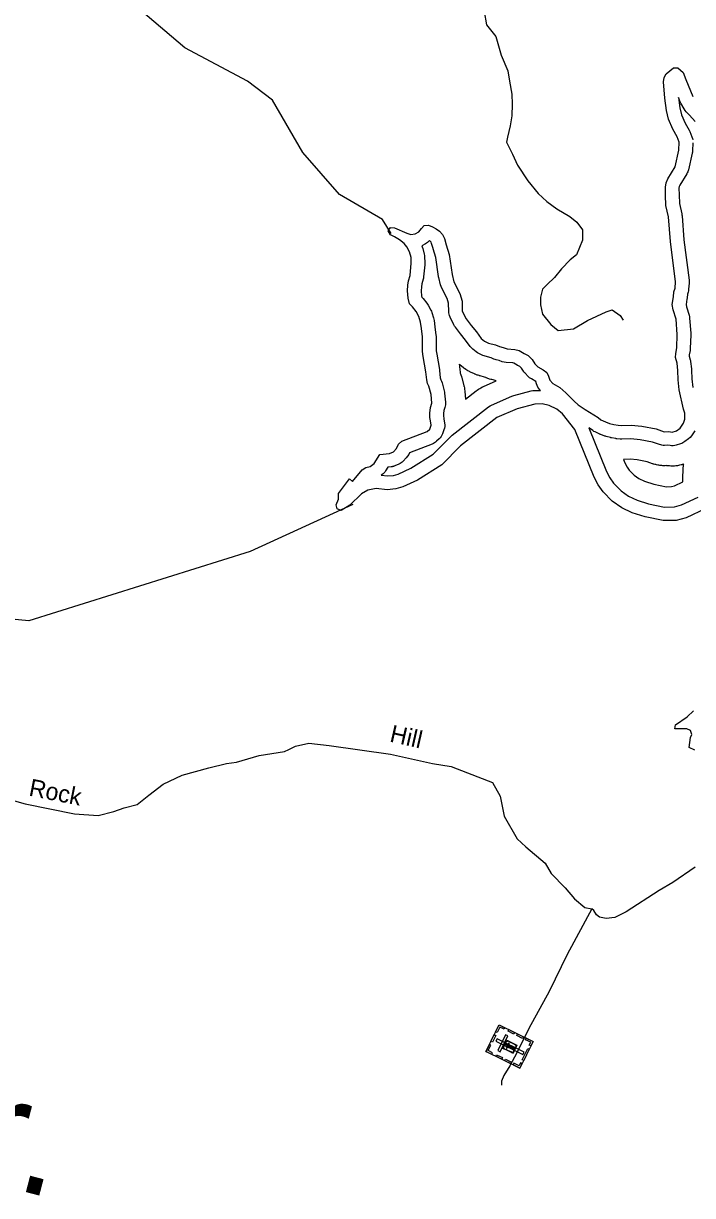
# Model space of a CAD drawing. Extents: x 1113032 to 1302912, y 664689 to 832535.
# Drawn here: x 1142627 to 1146316, y 741484 to 747949 of the extents above; entities that cross this region are included whole.
import ezdxf

# ---------------------------------------------------------------- set-up
doc = ezdxf.new("R2010")
doc.units = 0
for name, color, linetype in [('Exist Cultural Cemetery CELL', 7, 'Continuous'), ('Exist Hydrographic Buffer Line', 7, 'Continuous'), ('Exist Hydrographic Creek Single Shore', 7, 'Continuous'), ('Exist Hydrographic Creek Single Shore Label', 7, 'Continuous'), ('Exist Hydrographic Lake Shore', 7, 'Continuous'), ('Exist Road Non-System Type 51', 7, 'Continuous'), ('Exist Road Non-System Type 51 Label', 7, 'Continuous')]:
    doc.layers.add(name, color=color, linetype=linetype)

msp = doc.modelspace()

# ---------------------------------------------------------------- linework, layer by layer
at = {"layer": 'Exist Cultural Cemetery CELL'}
for points in [[(1145177, 742279), (1145249.1, 742425.5), (1145436.5, 742333.3), (1145364.4, 742186.8)], [(1145281, 742409.9), (1145276.9, 742401.5), (1145253.2, 742413.2), (1145238.5, 742383.3), (1145230.3, 742387.4), (1145249.1, 742425.5)], [(1145330.7, 742375), (1145298.8, 742390.7), (1145302.9, 742399.1), (1145334.8, 742383.4)], [(1145203.8, 742333.5), (1145222.6, 742371.6), (1145231, 742367.5), (1145212.2, 742329.4)], [(1145238, 742348.6), (1145231.3, 742334.9), (1145380.5, 742261.5), (1145387.3, 742275.2)], [(1145241.9, 742284.4), (1145255.6, 742277.6), (1145298.2, 742364.3), (1145284.5, 742371.1)], [(1145269, 742297.1), (1145290.9, 742341.8), (1145348, 742313.7), (1145326.1, 742269)], [(1145300.7, 742337), (1145299.4, 742334.5), (1145292.2, 742338), (1145287.7, 742328.9), (1145285.2, 742330.1), (1145290.9, 742341.8)], [(1145315.8, 742326.4), (1145306.1, 742331.2), (1145307.3, 742333.7), (1145317.1, 742328.9)], [(1145379.2, 742351.1), (1145347.3, 742366.8), (1145351.4, 742375.2), (1145383.3, 742359.5)], [(1145424.5, 742309), (1145416, 742313.1), (1145424, 742329.3), (1145394.3, 742343.9), (1145398.3, 742352.1), (1145436.5, 742333.3)], [(1145208.9, 742263.3), (1145213, 742271.7), (1145189.3, 742283.3), (1145204, 742313.2), (1145195.8, 742317.2), (1145177, 742279)], [(1145278.7, 742292.3), (1145279.9, 742294.9), (1145272.7, 742298.4), (1145277.2, 742307.5), (1145274.7, 742308.7), (1145269, 742297.1)], [(1145277.1, 742313.7), (1145282.9, 742325.3), (1145285.4, 742324.1), (1145279.7, 742312.5)], [(1145287.6, 742318.3), (1145285.5, 742314.1), (1145331, 742291.8), (1145333.1, 742296)], [(1145295.3, 742284.1), (1145285.6, 742288.9), (1145286.8, 742291.5), (1145296.6, 742286.7)], [(1145288.7, 742298.7), (1145292.9, 742296.7), (1145305.9, 742323.1), (1145301.7, 742325.2)], [(1145310.4, 742276.7), (1145300.7, 742281.5), (1145301.9, 742284), (1145311.6, 742279.3)], [(1145329.7, 742276.4), (1145327.1, 742277.7), (1145324.7, 742272.8), (1145315.6, 742277.2), (1145314.4, 742274.7), (1145326.1, 742269)], [(1145330.6, 742319.1), (1145320.9, 742323.9), (1145322.1, 742326.4), (1145331.8, 742321.6)], [(1145329.8, 742283.2), (1145339.2, 742302.2), (1145341.8, 742300.9), (1145332.4, 742281.9)], [(1145344.4, 742306.2), (1145341.8, 742307.5), (1145344.2, 742312.4), (1145335.2, 742316.9), (1145336.4, 742319.4), (1145348, 742313.7)], [(1145376.8, 742233.3), (1145407.5, 742295.7), (1145415.9, 742291.6), (1145385.1, 742229.1)], [(1145263.4, 742236.5), (1145231.6, 742252.1), (1145235.7, 742260.5), (1145267.6, 742244.8)], [(1145312.9, 742212.1), (1145281, 742227.8), (1145285.2, 742236.2), (1145317, 742220.5)], [(1145376.3, 742211.2), (1145367.9, 742215.3), (1145359.9, 742199.1), (1145330.2, 742213.8), (1145326.1, 742205.6), (1145364.3, 742186.8)]]:
    msp.add_lwpolyline(points, close=True, dxfattribs=at)
at = {"layer": 'Exist Hydrographic Buffer Line'}
for points in [[(1146330.2, 747407.6), (1146299.7, 747443.1), (1146281.7, 747461.3), (1146275, 747469.1), (1146269.5, 747477.8), (1146251.8, 747509.8), (1146249.8, 747513.7), (1146248.1, 747517.6), (1146238.5, 747541.2), (1146246.4, 747483), (1146255.8, 747445.3), (1146275, 747399.4), (1146296.7, 747360), (1146298.6, 747356.2), (1146300.4, 747352.4), (1146312.5, 747322.9), (1146315.2, 747315.1), (1146317, 747307)], [(1146318, 747290.4), (1146315.6, 747246.1), (1146315, 747239.8), (1146313.9, 747233.6), (1146293.3, 747142.1), (1146291.7, 747136.1), (1146289.6, 747130.3), (1146287, 747124.6), (1146283.9, 747119.2), (1146246.2, 747058), (1146242.6, 747049.3), (1146241.2, 747040.7), (1146241.7, 747003.8), (1146243.5, 746955.8), (1146256.6, 746899.9), (1146257.6, 746894.3), (1146258.3, 746888.7), (1146268.7, 746754.9), (1146297, 746533.3), (1146297.6, 746525.2), (1146297.3, 746517), (1146294.2, 746483), (1146293.1, 746475.2), (1146291.1, 746467.5), (1146287.4, 746455.3), (1146285.9, 746435.1), (1146285.6, 746431.7), (1146285.1, 746428.3), (1146280.2, 746398.3), (1146281.9, 746386.4), (1146296.6, 746339.7), (1146298.7, 746331.5), (1146299.8, 746323.2), (1146306.4, 746240.1), (1146306.6, 746235.8), (1146306.6, 746231.4), (1146303.8, 746156.4), (1146303.4, 746151.1), (1146302.6, 746145.7), (1146298.2, 746121.3), (1146297.9, 746114.4), (1146303.2, 746094.1), (1146304.3, 746089.2), (1146305, 746084.3), (1146310, 746043.8), (1146310.3, 746040.2), (1146310.5, 746036.5), (1146311.5, 745989.5), (1146317.2, 745940.8)], [(1146328, 745701.5), (1146310, 745675.2), (1146302.7, 745666.2), (1146294.1, 745658.4), (1146273.7, 745642.5), (1146268.2, 745638.7), (1146262.4, 745635.3), (1146256.3, 745632.4), (1146249.9, 745630.2), (1146226.4, 745622.9), (1146218.1, 745620.8), (1146209.5, 745619.7), (1146200.8, 745619.6), (1146192.2, 745620.5), (1146180.2, 745622.4), (1146161.5, 745621.8), (1146154.4, 745621.9), (1146147.4, 745622.7), (1146140.5, 745624.1), (1146133.7, 745626.2), (1146095.4, 745639.9), (1146026.6, 745653.3), (1145975.4, 745657.7), (1145926.4, 745656.2), (1145921.6, 745656.3), (1145916.8, 745656.6), (1145898.3, 745658.4), (1145895.5, 745658.8), (1145892.7, 745659.2), (1145869, 745663.4), (1145865.9, 745664), (1145862.9, 745664.8), (1145839.7, 745670.9), (1145836.4, 745671.9), (1145833.1, 745673), (1145810.6, 745681.2), (1145807.4, 745682.4), (1145804.3, 745683.8), (1145778.7, 745695.9), (1145772.4, 745699.3), (1145766.5, 745703.2), (1145753.4, 745712.8), (1145744.2, 745718.5), (1145840.8, 745478.2), (1145859.2, 745443.6), (1145880.7, 745413.3), (1145922.1, 745371.1), (1145963.6, 745341.9), (1146010.6, 745319.6), (1146074, 745300.2), (1146161.8, 745281.9), (1146215.9, 745282.8), (1146254.7, 745293.2), (1146347.2, 745336.2)]]:
    msp.add_lwpolyline(points, dxfattribs=at)
for points in [[(1144634, 745453), (1144666.7, 745455.6), (1144692.2, 745463.1), (1144763.5, 745495.9), (1144886.4, 745573.7), (1144983, 745671.5), (1144986.6, 745674.8), (1144990.3, 745677.9), (1145191.8, 745834.7), (1145199.6, 745840), (1145208, 745844.3), (1145320.1, 745892.8), (1145325.1, 745894.7), (1145330.3, 745896.3), (1145426.6, 745922.4), (1145436, 745924.3), (1145445.7, 745925), (1145477.7, 745925.2), (1145474.4, 745928.7), (1145468.3, 745935.8), (1145463.1, 745943.7), (1145459, 745952.1), (1145455.9, 745961), (1145452.2, 745974.9), (1145427.3, 745988.5), (1145417.8, 745994.7), (1145409.3, 746002.2), (1145392.7, 746019.4), (1145388, 746024.8), (1145383.8, 746030.7), (1145372.9, 746047.5), (1145364, 746056.3), (1145352.1, 746062.6), (1145350.8, 746063.3), (1145349.6, 746064), (1145331, 746074.7), (1145324.3, 746076.4), (1145289, 746078.7), (1145277.9, 746080.3), (1145267.2, 746083.5), (1145249.2, 746090.4), (1145233.9, 746094), (1145227.2, 746095.8), (1145220.8, 746098.3), (1145205.2, 746105.1), (1145172.5, 746113.6), (1145166.3, 746115.5), (1145160.3, 746117.9), (1145138.5, 746127.9), (1145130.2, 746132.3), (1145122.5, 746137.7), (1145103.9, 746152.7), (1145096.6, 746159.4), (1145090.3, 746167), (1145065, 746201.7), (1145036.8, 746236.6), (1145036.3, 746237.2), (1145035.8, 746237.8), (1145008.2, 746273.4), (1145003.8, 746279.9), (1145000, 746286.7), (1144979.1, 746330), (1144976, 746337.4), (1144973.7, 746345.2), (1144972.2, 746353.2), (1144971.6, 746361.2), (1144970.8, 746406.9), (1144963.6, 746432.3), (1144933.2, 746489.2), (1144929.2, 746497.9), (1144926.4, 746507), (1144916.8, 746547.2), (1144916.1, 746550.5), (1144915.5, 746553.8), (1144900.1, 746658.5), (1144885.7, 746706.1), (1144885.4, 746707.1), (1144885.1, 746708.1), (1144877.4, 746736.2), (1144873.9, 746743), (1144870.1, 746747.7), (1144864.9, 746751.4), (1144860.8, 746746.8), (1144855.3, 746741.7), (1144849.4, 746737.3), (1144843, 746733.4), (1144822.5, 746722.4), (1144825.3, 746716.3), (1144828, 746708.3), (1144836.3, 746677.5), (1144837.9, 746669.6), (1144838.8, 746661.6), (1144840.3, 746629.7), (1144840.4, 746624), (1144840, 746618.4), (1144833, 746550.7), (1144832.1, 746544.5), (1144830.7, 746538.4), (1144823.6, 746512.7), (1144820.7, 746496.5), (1144819.2, 746474.5), (1144821.5, 746445.6), (1144822.6, 746441), (1144823.4, 746440.2), (1144827.5, 746436.1), (1144831.2, 746431.7), (1144850.9, 746406.5), (1144854.7, 746401.2), (1144858, 746395.7), (1144873.1, 746367.5), (1144875.9, 746361.5), (1144878.3, 746355.3), (1144888.1, 746324.9), (1144889.9, 746318.3), (1144891.1, 746311.5), (1144895.7, 746276.2), (1144895.8, 746275.9), (1144895.8, 746275.7), (1144901.4, 746230.4), (1144901.8, 746226.6), (1144902, 746222.8), (1144902.8, 746185.5), (1144902.8, 746184.1), (1144902.8, 746182.8), (1144902.3, 746143.9), (1144905.2, 746124.1), (1144920.1, 746041), (1144920.6, 746037.9), (1144921, 746034.8), (1144924.8, 745994.3), (1144925.7, 745989), (1144928.4, 745983.9), (1144932.1, 745976), (1144934.9, 745967.6), (1144947, 745921.9), (1144948.4, 745915.5), (1144949.2, 745909.1), (1144953.3, 745860.5), (1144953.6, 745852.8), (1144953, 745845.2), (1144951.7, 745837.6), (1144949.6, 745830.2), (1144944.5, 745815), (1144942.3, 745797), (1144942.8, 745784), (1144945.2, 745770.2), (1144945.3, 745769.5), (1144945.4, 745768.8), (1144949, 745745.3), (1144949.9, 745736), (1144949.5, 745726.6), (1144948, 745717.4), (1144945.4, 745708.4), (1144937.3, 745686.1), (1144933.9, 745678.1), (1144929.5, 745670.6), (1144924.4, 745663.6), (1144918.5, 745657.3), (1144904.9, 745644.5), (1144899.4, 745639.7), (1144893.4, 745635.5), (1144887.1, 745631.9), (1144880.4, 745628.9), (1144755.1, 745580.2), (1144751.2, 745572), (1144745.2, 745561.6), (1144737.5, 745552.3), (1144721, 745535.1), (1144715.5, 745529.9), (1144709.5, 745525.3), (1144703.1, 745521.3), (1144696.3, 745518), (1144674.4, 745508.7), (1144671.7, 745507.7), (1144669.1, 745506.7), (1144668.3, 745506.5), (1144667.5, 745506.2), (1144664.7, 745505.5), (1144662, 745504.7), (1144661.2, 745504.5), (1144660.3, 745504.3), (1144657.5, 745503.9), (1144654.8, 745503.4), (1144636.6, 745501), (1144623.5, 745480.7), (1144619.4, 745475), (1144614.9, 745469.7), (1144609.8, 745464.9), (1144604.3, 745460.6), (1144599.4, 745457)], [(1145064.3, 745877.4), (1145123, 745923.1), (1145125.8, 745925.2), (1145128.7, 745927.2), (1145136.6, 745932.6), (1145142.5, 745936.3), (1145148.7, 745939.8), (1145157.2, 745944.1), (1145160.3, 745945.6), (1145163.6, 745947.1), (1145232.7, 745977), (1145231, 745977.5), (1145227.1, 745979), (1145216.4, 745983.1), (1145208.6, 745984.9), (1145206.1, 745985.5), (1145203.6, 745986.1), (1145197, 745988), (1145192, 745989.5), (1145187.2, 745991.2), (1145180.7, 745993.7), (1145178.3, 745994.6), (1145176, 745995.7), (1145168.5, 745998.9), (1145144.3, 746005.2), (1145142, 746005.8), (1145139.7, 746006.5), (1145133.5, 746008.4), (1145128.9, 746009.9), (1145124.3, 746011.6), (1145118.3, 746014.1), (1145116.1, 746015), (1145113.9, 746016), (1145092, 746025.9), (1145088.9, 746027.4), (1145085.8, 746029), (1145077.5, 746033.5), (1145071.4, 746036.9), (1145065.5, 746040.8), (1145057.9, 746046.2), (1145055.1, 746048.3), (1145052.3, 746050.4), (1145033.6, 746065.5), (1145030.8, 746067.8), (1145028.8, 746069.6), (1145030.4, 746060.8), (1145030.6, 746059.6), (1145030.7, 746058.5), (1145031.2, 746055.4), (1145031.6, 746053.1), (1145031.9, 746050.7), (1145032.2, 746047.6), (1145032.3, 746046.5), (1145032.5, 746045.3), (1145034.8, 746020.7), (1145036.3, 746017.1), (1145038.5, 746010.9), (1145041.3, 746002.6), (1145042.3, 745999.5), (1145043.1, 745996.3), (1145055.2, 745950.6), (1145055.8, 745948.2), (1145056.4, 745945.9), (1145057.8, 745939.5), (1145058.7, 745934.7), (1145059.5, 745929.8), (1145060.3, 745923.3), (1145060.6, 745920.9), (1145060.8, 745918.5)], [(1146172.4, 745394.1), (1146200.3, 745394.5), (1146216.3, 745398.8), (1146262.9, 745420.5), (1146262.8, 745421.5), (1146262.5, 745427.2), (1146262.4, 745434.8), (1146262.4, 745437.7), (1146262.5, 745440.5), (1146264.3, 745490.6), (1146264.5, 745492.8), (1146264.6, 745495), (1146265, 745500.9), (1146265.5, 745505.3), (1146266.1, 745509.7), (1146267, 745515.5), (1146267.3, 745517.7), (1146267.5, 745518.3), (1146259.6, 745515.9), (1146256.5, 745515), (1146253.4, 745514.2), (1146245, 745512.1), (1146238.7, 745510.7), (1146232.3, 745509.7), (1146223.7, 745508.6), (1146217.3, 745508), (1146210.8, 745507.7), (1146202.2, 745507.6), (1146195.7, 745507.7), (1146189.3, 745508.2), (1146180.7, 745509.1), (1146177.5, 745509.5), (1146174.3, 745509.9), (1146173, 745510.1), (1146165.3, 745509.9), (1146162.7, 745509.8), (1146160, 745509.8), (1146152.9, 745509.9), (1146147.6, 745510.1), (1146142.3, 745510.6), (1146135.3, 745511.3), (1146130, 745512), (1146124.8, 745513), (1146117.9, 745514.4), (1146112.7, 745515.6), (1146107.6, 745517), (1146100.8, 745519.1), (1146098.3, 745519.9), (1146095.8, 745520.8), (1146065.6, 745531.6), (1146011.1, 745542.2), (1145972.3, 745545.5), (1145934.9, 745544.4), (1145942.5, 745525.5), (1145954.7, 745502.6), (1145966.9, 745485.4), (1145994.9, 745456.9), (1146020.3, 745439), (1146051.3, 745424.3), (1146101.9, 745408.8)]]:
    msp.add_lwpolyline(points, close=True, dxfattribs=at)
at = {"layer": 'Exist Hydrographic Creek Single Shore'}
for points in [[(1144653.9, 746790.7), (1144606.9, 746867.1), (1144368.9, 747006.4), (1144166.8, 747237), (1144000.8, 747525.9), (1143861.8, 747630.4), (1143516.8, 747814.6), (1143272.8, 748023)], [(1144442.9, 745294.9), (1143876.9, 745037.1), (1142656.9, 744654.5), (1142524, 744666.9), (1141821.9, 744904.2), (1141673.9, 744986), (1141446.9, 745200.6), (1141013.9, 745488.3), (1140852.9, 745717.9), (1140649.9, 746158.5), (1140465.9, 746421.5), (1140331.4, 746554.3)]]:
    msp.add_lwpolyline(points, dxfattribs=at)
at = {"layer": 'Exist Hydrographic Lake Shore'}
for points in [[(1146115.3, 745712.5), (1146159, 745696.8), (1146185, 745697.6), (1146204.2, 745694.5), (1146227.7, 745701.8), (1146248.1, 745717.6), (1146266.2, 745743.9), (1146273.1, 745766.8), (1146272.8, 745798.7), (1146265.6, 745821.4), (1146243.1, 745928.7), (1146236.6, 745984.3), (1146235.5, 746034.8), (1146230.6, 746075.3), (1146222.6, 746106.2), (1146223.4, 746129.4), (1146228.8, 746159.2), (1146231.6, 746234.2), (1146225, 746317.3), (1146208.5, 746369.7), (1146204.3, 746399), (1146211.1, 746440.4), (1146213.2, 746469.2), (1146219.5, 746489.8), (1146222.6, 746523.8), (1146194.1, 746747.2), (1146183.5, 746882.8), (1146168.9, 746945.7), (1146166.7, 747001.9), (1146166.1, 747046.3), (1146170, 747069.9), (1146179.1, 747092.1), (1146220.1, 747158.6), (1146240.7, 747250.1), (1146243.1, 747294.4), (1146231, 747323.9), (1146207.4, 747366.8), (1146184.3, 747421.6), (1146172.7, 747468.9), (1146163.3, 747537.1), (1146155, 747627.4), (1146159.5, 747650.9), (1146171.2, 747671.7), (1146211.9, 747704.8), (1146235.6, 747705.2), (1146264, 747679.1), (1146278.9, 747640.6), (1146317.5, 747546)], [(1144645, 745577.7), (1144667, 745587.1), (1144683.5, 745604.2), (1144695, 745628.4), (1144712.8, 745644.3), (1144853.3, 745698.8), (1144866.8, 745711.7), (1144874.9, 745734), (1144871.3, 745757.5), (1144868.1, 745776), (1144867.1, 745800), (1144871, 745831.7), (1144878.6, 745854.2), (1144874.5, 745902.7), (1144862.4, 745948.4), (1144854, 745964), (1144850.4, 745984.1), (1144846.3, 746027.8), (1144831.2, 746112), (1144827.2, 746138.9), (1144827.8, 746183.8), (1144827, 746221.1), (1144821.4, 746266.4), (1144816.8, 746301.8), (1144806.9, 746332.1), (1144791.8, 746360.3), (1144772.2, 746385.5), (1144754.6, 746401.9), (1144747.2, 746434.1), (1144744, 746474), (1144746.1, 746505.8), (1144750.4, 746529.4), (1144758.4, 746558.4), (1144765.4, 746626.1), (1144763.8, 746658), (1144755.5, 746688.8), (1144740.6, 746717.1), (1144725.6, 746735.7), (1144701.1, 746756.3), (1144672, 746771.4), (1144651.3, 746783.4), (1144636.9, 746805.2), (1144650.1, 746823.9), (1144672.9, 746821.7), (1144739.9, 746792.8), (1144762.7, 746785.8), (1144786.4, 746788.1), (1144807.4, 746799.4), (1144822.4, 746818), (1144836.2, 746835.4), (1144860.1, 746835.8), (1144882.5, 746827.6), (1144902.3, 746817), (1144921.6, 746802.9), (1144937, 746784.6), (1144947.8, 746763.1), (1144957.4, 746727.9), (1144973.5, 746674.9), (1144989.7, 746564.7), (1144999.4, 746524.6), (1145033.6, 746460.5), (1145045.6, 746418), (1145046.6, 746362.6), (1145067.5, 746319.4), (1145095.1, 746283.7), (1145124.5, 746247.3), (1145150.9, 746211.1), (1145169.5, 746196.1), (1145191.4, 746186.2), (1145229.8, 746176.2), (1145250.7, 746167.1), (1145271.1, 746162.3), (1145294, 746153.6), (1145336.1, 746150.7), (1145359.4, 746144.9), (1145387, 746129), (1145409, 746117.4), (1145431.5, 746094.9), (1145446.7, 746071.5), (1145463.3, 746054.3), (1145492.4, 746038.3), (1145511.8, 746024.7), (1145522.1, 746003.3), (1145528.3, 745980.8), (1145544.8, 745963.7), (1145585.1, 745941.4), (1145617.3, 745912.6), (1145663.4, 745865.8), (1145685.4, 745845), (1145723.1, 745819.4), (1145795.3, 745775.1), (1145810.8, 745763.7), (1145836.4, 745751.6), (1145858.8, 745743.4), (1145882.1, 745737.3), (1145905.8, 745733.1), (1145924.2, 745731.2), (1145977.4, 745732.8), (1146036.9, 745727.7), (1146115.3, 745712.5)], [(1146389.4, 745273.1), (1146280.4, 745222.4), (1146226.4, 745207.9), (1146154.6, 745206.8), (1146055.4, 745227.5), (1145983.4, 745249.5), (1145925.7, 745276.9), (1145873.4, 745313.7), (1145823, 745365), (1145795.3, 745404.1), (1145772.7, 745446.5), (1145667.2, 745708.9), (1145599.3, 745796.3), (1145568.4, 745821.4), (1145525.1, 745842), (1145486, 745850.2), (1145446.2, 745850), (1145349.9, 745823.9), (1145237.8, 745775.5), (1145036.4, 745618.7), (1144933.7, 745514.9), (1144799.4, 745429.9), (1144718.6, 745392.7), (1144680.4, 745381.4), (1144632.6, 745377.6), (1144571.9, 745384.7), (1144525.3, 745374.5), (1144490.9, 745354.3), (1144426.8, 745292.8), (1144377.7, 745263), (1144356.5, 745272.1), (1144350.4, 745294.6), (1144364.1, 745325.4), (1144364.7, 745357.2), (1144424.1, 745437.1), (1144441.9, 745423.2), (1144494.6, 745486.9), (1144515, 745499.3), (1144538.1, 745505.3), (1144560.5, 745521.4), (1144592.5, 745570.9), (1144645, 745577.7)], [(1146329.1, 743941.1), (1146296.7, 743954.9), (1146304.4, 744010.1), (1146311.9, 744026.6), (1146305.1, 744049), (1146284.2, 744059.3), (1146218, 744058.8), (1146221.5, 744081), (1146287, 744125.2), (1146322.1, 744157.1)]]:
    msp.add_lwpolyline(points, dxfattribs=at)
at = {"layer": 'Exist Road Non-System Type 51'}
for points in [[(1145174.6, 748232.8), (1145171.8, 748178.1), (1145147.5, 748099.9), (1145166.6, 748014.6), (1145180.5, 747941.6), (1145230.9, 747877.2), (1145260.5, 747774.6), (1145297, 747687.6)], [(1145297, 747687.6), (1145307.4, 747631.2), (1145319.6, 747559.9), (1145321.3, 747504.3), (1145319.6, 747439.9), (1145310.9, 747384.2), (1145295.3, 747321.6), (1145290, 747293.8)], [(1145290, 747293.8), (1145323.1, 747228), (1145350.9, 747167.1), (1145408.3, 747080.2), (1145465.6, 747010.6), (1145512.5, 746967.1), (1145568.2, 746927.1), (1145639.4, 746883.6), (1145677.7, 746854), (1145709, 746810.5)], [(1145709, 746810.5), (1145709, 746753.1), (1145675.9, 746673.1), (1145641.2, 746645.3), (1145594.2, 746596.6), (1145554.3, 746547.9), (1145514.3, 746509.6), (1145488.2, 746483.5), (1145477.8, 746440), (1145477.8, 746396.5), (1145488.2, 746346.1), (1145535.1, 746288.7), (1145575.1, 746255.6), (1145660.3, 746264.3), (1145736.8, 746311.3), (1145839.3, 746358.3), (1145872.4, 746370.4)], [(1145872.4, 746370.4), (1145917.2, 746338.8), (1145932.9, 746312.7)], [(1142300.8, 743737.9), (1142636, 743643.9), (1142908.6, 743589.9), (1143039.5, 743580.4), (1143125.9, 743603), (1143182.3, 743621.8), (1143253.8, 743640.6), (1143317.7, 743693.3), (1143396.7, 743753.5), (1143502, 743802.4), (1143648.6, 743843.8), (1143746.4, 743866.4), (1143801.9, 743875.4), (1143926.9, 743911.5), (1144066, 743934.1), (1144089.8, 743945.3), (1144126.6, 743962), (1144201.1, 743979.9), (1144312.8, 743966.5), (1144649.7, 743919.2), (1144882.3, 743866.3), (1144985.8, 743851.3), (1145132.2, 743794.1), (1145213.8, 743762), (1145255.7, 743686.6), (1145277.9, 743575.9), (1145348.2, 743451.7), (1145396.9, 743408.1), (1145502.6, 743316.8), (1145537.3, 743260.9), (1145613.4, 743181.5), (1145666, 743121.3), (1145722.4, 743072.4), (1145761, 743065)], [(1146330.5, 743294.5), (1146207.6, 743210), (1146132.3, 743166.2), (1145950.7, 743049.4), (1145887.7, 743017.5), (1145839.7, 743012.9), (1145803.7, 743019.9), (1145786.2, 743032.3), (1145771, 743056.9), (1145761, 743065)], [(1145761, 743065), (1145625.6, 742813), (1145525.4, 742609.9), (1145413.3, 742405), (1145347.3, 742270.8), (1145309.1, 742200), (1145275.5, 742146.8), (1145262.7, 742115.2), (1145262, 742093.3)]]:
    msp.add_lwpolyline(points, dxfattribs=at)

# ---------------------------------------------------------------- texts
at = {"layer": 'Exist Hydrographic Creek Single Shore Label'}
msp.add_text('Cr.', height=600, rotation=345.39277, dxfattribs=at).set_placement((1141749.9, 741735.3))
at = {"layer": 'Exist Road Non-System Type 51 Label'}
for s, rotation, p in [('Hill', 347.18704, (1144641.7, 743988.9)), ('Rock', 348.7906, (1142652.1, 743690.9))]:
    msp.add_text(s, height=95, rotation=rotation, dxfattribs=at).set_placement(p)

doc.saveas('drawing.dxf')
